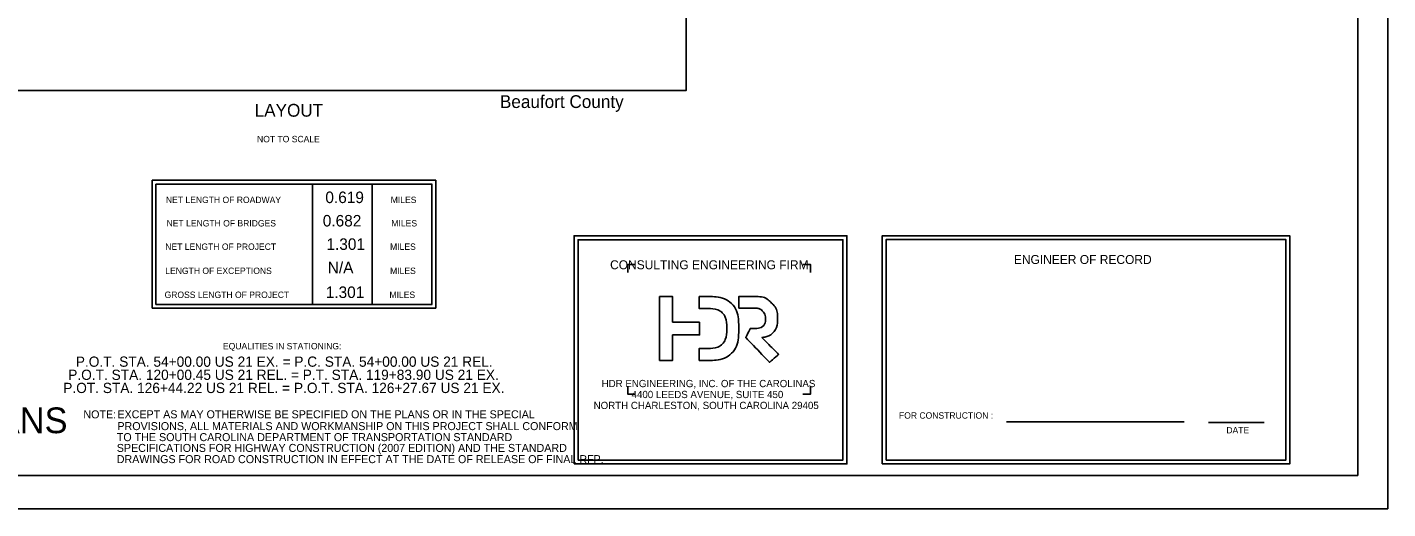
# Model space of a CAD drawing. Extents: x 9303 to 2295726, y 15071 to 323177.
# Drawn here: x 2065088 to 2295726, y 85015 to 166749 of the extents above; entities that cross this region are included whole.
import ezdxf

# ---------------------------------------------------------------- set-up
doc = ezdxf.new("R2010")
doc.units = 0
for name, color, linetype in [('RD_EX_DV_Prop_txCode', 7, 'Continuous'), ('RD_EX_H2O_txCode', 7, 'Continuous'), ('RD_SHT_Bndy', 7, 'Continuous'), ('RD_SHT_ID', 7, 'Continuous'), ('RD_SHT_TX', 7, 'Continuous')]:
    doc.layers.add(name, color=color, linetype=linetype)

msp = doc.modelspace()

# ---------------------------------------------------------------- linework, layer by layer
at = {"layer": 'RD_EX_DV_Prop_txCode'}
for p, q in [((2134353, 140767), (2086268, 140767)), ((2086268, 140767), (2086268, 119062)), ((2134353, 119062), (2134353, 140767)), ((2133712, 140116), (2086919, 140116)), ((2086919, 140116), (2086919, 119702)), ((2113454, 119702), (2113454, 140116)), ((2123555, 119702), (2123555, 140116)), ((2133702, 119702), (2133702, 140116)), ((2086268, 119062), (2134353, 119062)), ((2086919, 119707), (2133712, 119713)), ((2231094, 99765), (2261186, 99765)), ((2265333, 99643), (2274770, 99643))]:
    msp.add_line(p, q, dxfattribs=at)
for points in [[(2041148, 237372), (2176773, 237372), (2176773, 155997), (2041148, 155997)], [(2157793, 92647), (2204042, 92647), (2204042, 131361), (2157793, 131361)], [(2158465, 93298), (2203370, 93298), (2203370, 130689), (2158465, 130689)], [(2210038, 92647), (2279117, 92647), (2279117, 131361), (2210038, 131361)], [(2210689, 93298), (2278465, 93298), (2278465, 130710), (2210689, 130710)]]:
    msp.add_lwpolyline(points, close=True, dxfattribs=at)
at = {"layer": 'RD_EX_H2O_txCode'}
msp.add_lwpolyline([(1906006, 323177), (2295726, 323177), (2295726, 85015), (1906006, 85015)], close=True, dxfattribs=at)
at = {"layer": 'RD_SHT_Bndy'}
for p, q in [((2290622, 90681), (2290622, 318018)), ((1927966, 90681), (2290622, 90681))]:
    msp.add_line(p, q, dxfattribs=at)
at = {"layer": 'RD_SHT_ID'}
for points in [[(2166877, 125124), (2166877, 126455), (2168209, 126455)], [(2196551, 126455), (2197882, 126455), (2197882, 125124)], [(2168209, 104498), (2166877, 104498), (2166877, 105830)], [(2197882, 105830), (2197882, 104498), (2196551, 104498)]]:
    msp.add_lwpolyline(points, dxfattribs=at)
for points in [[(2179052, 116703), (2179052, 116703), (2174493, 116703), (2174493, 116703), (2174493, 116703), (2174493, 116703), (2174493, 121036), (2174493, 121036), (2174493, 121036), (2174493, 121036), (2172296, 121036), (2172296, 121036), (2172296, 121036), (2172296, 121036), (2172296, 110199), (2172296, 110199), (2172296, 110199), (2172296, 110199), (2174493, 110199), (2174493, 110199), (2174493, 110199), (2174493, 110199), (2174493, 114535), (2174493, 114535), (2174493, 114535), (2174493, 114535), (2179052, 114535), (2179052, 114535), (2179052, 114535), (2179052, 114535), (2179052, 116703), (2179052, 116703)], [(2185697, 115624), (2185697, 115624), (2185697, 115630), (2185697, 115630), (2185697, 115630), (2185697, 115630), (2185696, 115630), (2185696, 115630), (2185696, 115630), (2185689, 118763), (2183412, 121036), (2180276, 121036), (2180276, 121036), (2180276, 121036), (2178995, 121036), (2178995, 121036), (2178995, 121036), (2178995, 121036), (2178995, 119002), (2178995, 119002), (2178995, 119002), (2178995, 119002), (2180276, 119002), (2180276, 119002), (2180276, 119002), (2182267, 119002), (2183658, 117613), (2183662, 115624), (2183662, 115624), (2183658, 113634), (2182267, 112233), (2180276, 112233), (2180276, 112233), (2180276, 112233), (2178995, 112233), (2178995, 112233), (2178995, 112233), (2178995, 112233), (2178995, 110199), (2178995, 110199), (2178995, 110199), (2178995, 110199), (2180276, 110199), (2180276, 110199), (2180276, 110199), (2183412, 110199), (2185689, 112484), (2185696, 115618), (2185696, 115618), (2185696, 115618), (2185697, 115618), (2185697, 115618), (2185697, 115618), (2185697, 115618), (2185697, 115624), (2185697, 115624)], [(2185694, 119087), (2185694, 119087), (2188141, 119087), (2188141, 119087), (2188141, 119087), (2188879, 119087), (2189379, 118932), (2189739, 118578), (2189739, 118578), (2190067, 118254), (2190238, 117828), (2190238, 117347), (2190238, 117347), (2190238, 116251), (2189293, 115599), (2188240, 115599), (2188240, 115599), (2188240, 115599), (2187629, 115599), (2187629, 115599), (2187629, 115599), (2187629, 115599), (2186912, 114051), (2186912, 114051), (2186912, 114051), (2186912, 114051), (2190915, 109901), (2190915, 109901), (2190915, 109901), (2190915, 109901), (2192472, 111208), (2192472, 111208), (2192472, 111208), (2192472, 111208), (2189635, 114071), (2189635, 114071), (2189635, 114071), (2191203, 114363), (2192271, 115795), (2192271, 117304), (2192271, 117304), (2192271, 118434), (2191950, 119305), (2191145, 120062), (2191145, 120062), (2190311, 120847), (2189384, 121036), (2187989, 121036), (2187989, 121036), (2187989, 121036), (2185694, 121036), (2185694, 121036), (2185694, 121036), (2185694, 121036), (2185694, 119087), (2185694, 119087)]]:
    msp.add_open_spline(points, degree=3, dxfattribs=at)

# ---------------------------------------------------------------- texts
at = {"layer": 'RD_EX_DV_Prop_txCode'}
for s, height, p in [('Beaufort County', 2170.5, (2145223, 153033)), ('LAYOUT', 2170.5, (2103644, 151559)), ('NOT TO SCALE', 1085.28, (2104045, 147218)), ('0.619', 1953.5, (2115628, 136899)), ('NET LENGTH OF ROADWAY', 1085.28, (2088601, 136903)), ('MILES', 1085.3, (2126711, 136903)), ('NET LENGTH OF BRIDGES', 1085.28, (2088710, 132931)), ('0.682', 1953.5, (2115191, 132927)), ('MILES', 1085.3, (2126819, 132931)), ('NET LENGTH OF PROJECT', 1085.28, (2088493, 128959)), ('1.301', 1953.5, (2115811, 128955)), ('MILES', 1085.3, (2126602, 128959)), ('N/A', 1953.5, (2116036, 124983)), ('CONSULTING ENGINEERING FIRM', 1519.36, (2163896, 125671)), ('ENGINEER OF RECORD', 1519.36, (2232340, 126562)), ('LENGTH OF EXCEPTIONS', 1085.28, (2088493, 124868)), ('MILES', 1085.3, (2126602, 124868)), ('1.301', 1953.5, (2115692, 120794)), ('GROSS LENGTH OF PROJECT', 1085.28, (2088373, 120798)), ('MILES', 1085.3, (2126494, 120798)), ('HDR ENGINEERING, INC. OF THE CAROLINAS', 1231.47, (2162460, 105660)), ('4400 LEEDS AVENUE, SUITE 450', 1231.47, (2167539, 103804)), ('NOTE:', 1356.6, (2074612, 100366)), ('EXCEPT AS MAY OTHERWISE BE SPECIFIED ON THE PLANS OR IN THE SPECIAL ', 1356.55, (2080373, 100379)), ('NORTH CHARLESTON, SOUTH CAROLINA 29405', 1231.47, (2161107, 101947)), ('PROVISIONS, ALL MATERIALS AND WORKMANSHIP ON THIS PROJECT SHALL CONFORM ', 1356.55, (2080379, 98371)), ('FOR CONSTRUCTION :', 1085.28, (2212866, 100315)), ('TO THE SOUTH CAROLINA DEPARTMENT OF TRANSPORTATION STANDARD ', 1356.55, (2080280, 96501)), ('DATE', 1085.3, (2268359, 97816)), ('SPECIFICATIONS FOR HIGHWAY CONSTRUCTION (2007 EDITION) AND THE STANDARD', 1356.55, (2080270, 94671)), ('DRAWINGS FOR ROAD CONSTRUCTION IN EFFECT AT THE DATE OF RELEASE OF FINAL RFP.', 1356.55, (2080270, 92767))]:
    msp.add_text(s, height=height, dxfattribs=at).set_placement(p)
msp.add_text('CONCEPTUAL PLANS', height=4364.86, rotation=360, dxfattribs=at).set_placement((2011270, 97851))
at = {"layer": 'RD_SHT_TX'}
for s, height, p in [('EQUALITIES IN STATIONING:', 1085.28, (2098268, 112078)), ('P.O.T. STA. 54+00.00 US 21 EX. = P.C. STA. 54+00.00 US 21 REL.', 1736.42, (2073324, 109121)), ('P.O.T. STA. 120+00.45 US 21 REL. = P.T. STA. 119+83.90 US 21 EX.', 1736.42, (2072041, 106891)), ('P.OT. STA. 126+44.22 US 21 REL. = P.O.T. STA. 126+27.67 US 21 EX.', 1736.42, (2071196, 104661))]:
    msp.add_text(s, height=height, dxfattribs=at).set_placement(p)

doc.saveas('drawing.dxf')
